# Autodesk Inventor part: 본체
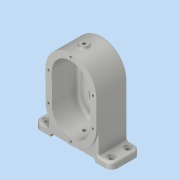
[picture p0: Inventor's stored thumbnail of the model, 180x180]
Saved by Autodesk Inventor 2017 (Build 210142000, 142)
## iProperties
Part Number: 본체
Material: 알루미늄 6061
Document SubType Name: Modeling
Designer: MRC
Density: 2.7 g/cm^3
Appearance: 알루미늄 - 평지
Mass: 756.754 g
Surface Area: 581.829 cm^2
Volume: 280.279 cm^3
Author: MRC
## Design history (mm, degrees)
sketch "스케치1"
  geometry: L1 (0, 0)-(0, -45); L2 (-40, 0)-(-40, -45); L3 (40, -45)-(40, 0); A1 r 40 centre (0, 0) between (40, 0) and (-40, 0); A2 r 40 centre (0, -45) between (-40, -45) and (40, -45); 2 further points
  constraints: 8 end point, 4 point on circle, 4 tangent, 2 centre point, 1 coincident, 1 midpoint, 1 parallel, 1 vertical
  dimensions: "d1" = 80 distance between parallel lines of L2 L3; "d2" = 45 distance of L1.start L1.end
extrude "돌출1" new body sketch "스케치1" distance "d3" = 49; taper "d4" = 0 deg
feature "쉘1" dims "d5" = 8, "d6" = 10
sketch "스케치2"
  geometry: L1 (0, 0)-(0, -45); L2 (-26, 0)-(-26, -45); L3 (26, -45)-(26, 0); A1 r 26 centre (0, 0) between (26, 0) and (-26, 0); A2 r 26 centre (0, -45) between (-26, -45) and (26, -45); 1 further point
  constraints: 8 end point, 4 point on circle, 4 tangent, 2 centre point, 1 midpoint, 1 parallel, 1 vertical
  dimensions: "d7" = 52 distance between parallel lines of L2 L3; "d8" = 45 distance of L1.start L1.end
extrude "돌출2" join sketch "스케치2" distance "d9" = 11; taper "d10" = 0 deg
sketch "스케치3"
  geometry: L1 (-26, 0)-(-26, -45) reference; L2 (26, -45)-(26, 0) reference; L3 (-26, -30)-(26, -30); A1 r 26 centre (0, -45) between (-26, -45) and (26, -45) reference; A2 r 26 centre (0, 0) between (26, 0) and (-26, 0) reference; 1 further point
  constraints: 2 end point, 2 point on line, 1 horizontal
  dimensions: "d11" = 30 distance from line of L3 point (0, 0)
extrude "돌출3" cut sketch "스케치3" distance "d12" = 3; taper "d13" = 0 deg
hole "구멍1" diameter "d16" = 22; stored, may be unused: countersink angle "d20" = 90 deg, drill point angle "d22" = 118 deg; dims "d14" = 10, "d15" = 10, "d17" = 6, "d18" = 28, "d19" = 4, "d21" = 8
sketch "스케치4"
  geometry: C1 r 14 at (0, 45); 1 further point
  constraints: 1 centre point, 1 coincident
  dimensions: "d23" = 28 diameter of C1
extrude "돌출4" cut sketch "스케치4" distance "d24" = 8; taper "d25" = 0 deg
hole "구멍2" diameter "d28" = 20; stored, may be unused: countersink angle "d32" = 90 deg, drill point angle "d34" = 0 deg; dims "d29" = 6, "d30" = 28, "d31" = 8, "d33" = 12, "d149" = 10, "d150" = 10
node "작업 평면3"
  node "작업 평면2"
sketch "스케치5"
  geometry: C1 r 6 at (0, -21); 1 further point
  constraints: 1 centre point, 1 vertical alignment
  dimensions: "d37" = 12 diameter of C1; "d38" = 21 distance of C1.centre point (0, 0)
extrude "돌출5" join sketch "스케치5" stored distance "d39" = 8; taper "d40" = 0 deg
hole "구멍3" diameter "d43" = 4.917; stored, may be unused: countersink angle "d47" = 90 deg, drill point angle "d49" = 0 deg; dims "d41" = 10, "d42" = 10, "d44" = 12, "d45" = 28, "d46" = 4, "d48" = 17.1
sketch "스케치6"
  geometry: 2 further points
  constraints: 1 vertical alignment
  dimensions: "d50" = 20 distance of point (0, 20) point (0, 0)
hole "구멍4" sketch "스케치6" at (0, 20) diameter "d51" = 3.242; stored, may be unused: countersink angle "d55" = 90 deg, drill point angle "d57" = 118 deg; dims "d52" = 8, "d53" = 28, "d54" = 4, "d56" = 10
sketch "스케치7"
  geometry: L1 (-40, -82)-(-61, -82); L2 (-61, -82)-(-61, -92); L3 (-61, -92)-(-35, -92); L4 (-35, -92)-(-35, -87); L5 (-35, -87)-(35, -87); L6 (35, -87)-(35, -92); L7 (35, -92)-(61, -92); L8 (61, -92)-(61, -82); L9 (61, -82)-(40, -82); L10 (-40, -82)-(-40, -45); L11 (40, -82)-(40, -45); L12 (-40, 0)-(-40, -45) reference; L13 (40, -45)-(40, 0) reference; A1 r 40 centre (0, -45) between (-40, -45) and (40, -45) reference; A2 r 26 centre (0, -45) between (-26, -45) and (26, -45) reference; 2 further points
  constraints: 22 end point, 6 perpendicular, 4 point on line, 3 collinear, 2 point on circle, 2 vertical, 1 horizontal, 1 midpoint, 1 vertical alignment
  dimensions: "d62" = 70 distance of L4.end L5.end; "d63" = 5 distance between parallel lines of L3 L5; "d64" = 122 distance between parallel lines of L8 L2; "d65" = 10 distance of L1.end L2.end; "d66" = 47 distance from line of A2.centre L3
extrude "돌출6" join sketch "스케치7" distance "d67" = 46; taper "d68" = 0 deg
fillet "모깎기1" dims "d69" = 10
hole "구멍5" diameter "d72" = 6.6; stored, may be unused: countersink angle "d76" = 90 deg, drill point angle "d78" = 118 deg; dims "d70" = 10, "d71" = 10, "d73" = 6.6, "d74" = 11, "d75" = 2, "d77" = 10
hole "구멍6" diameter "d81" = 6.6; stored, may be unused: countersink angle "d85" = 90 deg, drill point angle "d87" = 118 deg; dims "d79" = 10, "d80" = 10, "d82" = 6.6, "d83" = 11, "d84" = 2, "d86" = 10
hole "구멍7" diameter "d90" = 6.6; stored, may be unused: countersink angle "d94" = 90 deg, drill point angle "d96" = 118 deg; dims "d88" = 10, "d89" = 10, "d91" = 6.6, "d92" = 11, "d93" = 2, "d95" = 10
hole "구멍8" diameter "d99" = 6.6; stored, may be unused: countersink angle "d103" = 90 deg, drill point angle "d105" = 118 deg; dims "d97" = 10, "d98" = 10, "d100" = 6.6, "d101" = 11, "d102" = 2, "d104" = 10
sketch "스케치9"
  geometry: C1 r 14 at (0, 0) reference; C2 r 14 at (0, -45) reference; 7 further points
  constraints: 4 horizontal alignment, 2 vertical alignment
  dimensions: "d116" = 34.99967 distance of C2.centre point (35, -45); "d117" = 35 distance of C2.centre point (0, -80); "d118" = 35 distance of C2.centre point (-35, -45); "d119" = 35 distance of point (0, 0) point (-35, 0); "d120" = 35 distance of point (0, 0) point (0, 35); "d121" = 34.99967 distance of point (35, 0) point (0, 0)
hole "구멍10" sketch "스케치9" at (0, -80), (35, -45), (35, 0), (0, 35), (-35, 0), (-35, -45) diameter "d122" = 3.242; stored, may be unused: countersink angle "d126" = 90 deg, drill point angle "d128" = 118 deg; dims "d123" = 8, "d124" = 11, "d125" = 2, "d127" = 10
sketch "스케치10"
  geometry: 2 further points
  constraints: 1 vertical alignment
  dimensions: "d129" = 21 distance of point (35, 49) point (35, 28)
hole "구멍11" sketch "스케치10" at (35, 28) diameter "d130" = 4.917; stored, may be unused: countersink angle "d134" = 90 deg, drill point angle "d136" = 0 deg; dims "d131" = 12, "d132" = 12, "d133" = 1, "d135" = 17.1
sketch "스케치11"
  geometry: L1 (-51, -92)-(-61, -92) reference; 2 further points
  constraints: 1 vertical alignment, 1 other
  dimensions: "d137" = 12 distance from line of point (0, -80) L1
feature "엠보싱1" sketch "스케치11" dims "d1" = 80, "d2" = 45, "d138" = 0.5, "d139" = 0
fillet "모깎기2" dims "d140" = 3
fillet "모깎기3" dims "d141" = 3
fillet "모깎기4" dims "d142" = 3
fillet "모깎기5" dims "d143" = 5
chamfer "모따기1" distance "d144" = 1; stored, may be unused: second distance "d145" = 2, angle "d146" = 45 deg
fillet "모깎기6" dims "d147" = 0.3
fillet "모깎기7" dims "d148" = 3
node "솔리드1"
pattern_circular "원형 패턴1" dims angle "d59" = 360 deg
node "투영된 루프1"
other parameters: "d36" = 3
